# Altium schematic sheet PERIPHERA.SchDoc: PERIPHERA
size A4; Revision: V2.0; SheetNumber: 7; SheetTotal: 7; Project: PY32F403v1xT_START
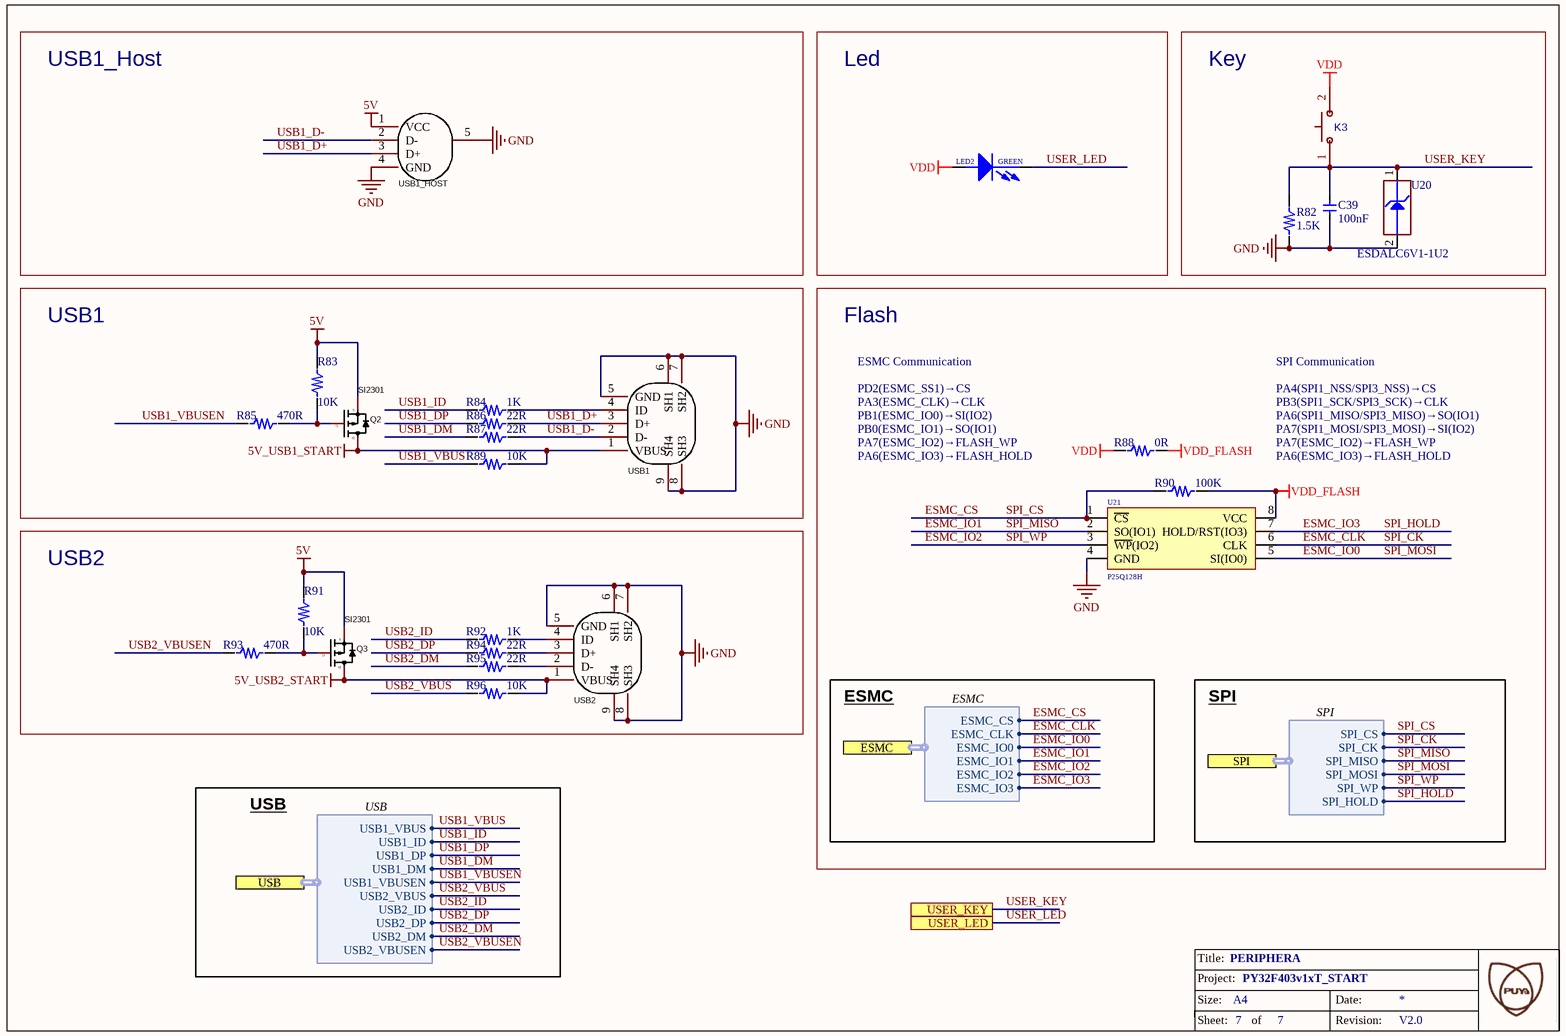
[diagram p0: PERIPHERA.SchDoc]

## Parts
C39  100nF  [C0603]
K3  1TS002B-2600-5001_key  [Switch]  (value not drawn)
LED2  GREEN  [0603_LED]
Q2  SI2301  [SOT-23-3_L2.9-W1.3-P1.90-LS2.4-BR]
Q3  SI2301  [SOT-23-3_L2.9-W1.3-P1.90-LS2.4-BR]
R82  1.5K  [R0603]
R83  10K  [R0603]
R84  1K  [R0603]
R85  470R  [R0603]
R86  22R  [R0603]
R87  22R  [R0603]
R88  0R  [R0603]
R89  10K  [R0603]
R90  100K  [R0603]
R91  10K  [R0603]
R92  1K  [R0603]
R93  470R  [R0603]
R94  22R  [R0603]
R95  22R  [R0603]
R96  10K  [R0603]
U20  value ESDALC6V1-1U2  [ESD_ST0201]  (hidden comment: ESD-TRANSIL)
U21  P25Q128H  [SOP8W_L]
USB1  Micro-B  [MICRO-USB-SMD_MICROXNJ]  (value not drawn)
USB1_HOST  Type-A  [USB-A-TH_AF-WJDG]  (value not drawn)
USB2  Micro-B  [MICRO-USB-SMD_MICROXNJ]  (value not drawn)

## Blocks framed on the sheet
USB1_Host: USB1_HOST
Led: LED2
Key: C39 K3 R82 U20
USB1: Q2 R83-R87 R89 USB1
Flash: R88 R90 U21
USB2: Q3 R91-R96 USB2

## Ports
ESMC (harness ESMC), SPI (harness SPI), USB (harness USB), USER_KEY, USER_LED

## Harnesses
ESMC: ESMC_IO2, ESMC_IO1, ESMC_IO0, ESMC_CS, ESMC_IO3, ESMC_CLK
SPI: SPI_MOSI, SPI_MISO, SPI_CS, SPI_CK, SPI_WP, SPI_HOLD
USB: USB2_VBUS, USB1_DM, USB1_DP, USB1_VBUS, USB2_ID, USB2_DP, USB2_DM, USB1_ID, USB2_VBUSEN, USB1_VBUSEN

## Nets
5V: Q2.2(S) Q3.2(S) R83.2 R91.2 USB1_HOST.1(VCC)
5V_USB1_START: Q2.3(D) R89.2 USB1.1(VBUS)
5V_USB2_START: Q3.3(D) R96.2 USB2.1(VBUS)
GND: C39.1 R82.1 U20.2(GND) U21.4(GND) USB1.5(GND) USB1.6(SH1) USB1.7(SH2) USB1.8(SH3) USB1.9(SH4) USB1_HOST.4(GND) USB1_HOST.5(SHLD) USB2.5(GND) USB2.6(SH1) USB2.7(SH2) USB2.8(SH3) USB2.9(SH4)
VDD: K3.2(B) LED2.1(ANODE) R88.1
VDD_FLASH: R88.2 R90.2 U21.8(VCC)
ESMC_CLK: U21.6(CLK) ; port ESMC.ESMC_CLK, port SPI.SPI_CK  [also labelled SPI_CK]
ESMC_CS: R90.1 U21.1(~{CS}) ; port ESMC.ESMC_CS, port SPI.SPI_CS  [also labelled SPI_CS]
ESMC_IO0: U21.5(SI(IO0)) ; port ESMC.ESMC_IO0, port SPI.SPI_MOSI  [also labelled SPI_MOSI]
ESMC_IO1: U21.2(SO(IO1)) ; port ESMC.ESMC_IO1, port SPI.SPI_MISO  [also labelled SPI_MISO]
ESMC_IO2: U21.3(~{WP}(IO2)) ; port ESMC.ESMC_IO2, port SPI.SPI_WP  [also labelled SPI_WP]
ESMC_IO3: U21.7(HOLD/RST(IO3)) ; port ESMC.ESMC_IO3, port SPI.SPI_HOLD  [also labelled SPI_HOLD]
USB1_D+: R86.2 USB1.3(D+) USB1_HOST.3(D+)
USB1_D-: R87.2 USB1.2(D-) USB1_HOST.2(D-)
USB1_DM: R87.1 ; port USB.USB1_DM
USB1_DP: R86.1 ; port USB.USB1_DP
USB1_ID: R84.1 ; port USB.USB1_ID
USB1_VBUS: R89.1 ; port USB.USB1_VBUS
USB1_VBUSEN: R85.1 ; port USB.USB1_VBUSEN
USB2_DM: R95.1 ; port USB.USB2_DM
USB2_DP: R94.1 ; port USB.USB2_DP
USB2_ID: R92.1 ; port USB.USB2_ID
USB2_VBUS: R96.1 ; port USB.USB2_VBUS
USB2_VBUSEN: R93.1 ; port USB.USB2_VBUSEN
USER_KEY: C39.2 K3.1(A) R82.2 U20.1(IO1) ; port USER_KEY
USER_LED: LED2.2(CATHODE) ; port USER_LED
NetQ2_1: Q2.1(G) R83.1 R85.2
NetQ3_1: Q3.1(G) R91.1 R93.2
NetR84_2: R84.2 USB1.4(ID)
NetR92_2: R92.2 USB2.4(ID)
NetR94_2: R94.2 USB2.3(D+)
NetR95_2: R95.2 USB2.2(D-)

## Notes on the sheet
- ESMC Communication
- SPI Communication
- PA3(ESMC_CLK)→CLK
- PB0(ESMC_IO1)→SO(IO1)
- PB1(ESMC_IO0)→SI(IO2)
- PD2(ESMC_SS1)→CS
- PA7(ESMC_IO2)→FLASH_WP
- PB3(SPI1_SCK/SPI3_SCK)→CLK
- PA6(SPI1_MISO/SPI3_MISO)→SO(IO1)
- PA7(SPI1_MOSI/SPI3_MOSI)→SI(IO2)
- PA4(SPI1_NSS/SPI3_NSS)→CS
- PA6(ESMC_IO3)→FLASH_HOLD
- ESMC
- SPI
- USB

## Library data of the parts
C39 = C0603: PCB DECAL: 0603
K3 = 1TS002B-2600-5001_key: BOM_Manufacturer: HYP; Contributor: LCSC
LED2 = PDI-E803_Dup1
Q2 Q3 = SI2301_C181086: Manufacturer: Hottech(合科泰); Add into BOM: yes; Type: P沟道; Drain Source Voltage (Vdss): 20V; Continuous Drain Current (Id): 2.3A; Power Dissipation (Pd): 1.25W; Drain Source On Resistance (RDS(on)@Vgs,Id): 120mΩ@4.5V,2.8A; Gate Threshold Voltage (Vgs(th)@Id): 1V@250uA
R82-R96 = R0603: PCB DECAL: 0603
U20 = ESD-TRANSIL: ESD protection 6V1; Internal_Part_Number: MCD-00170; Part_Type: Diode; Manufacturer: STMICROELECTRONICS; ECCN_US: EAR99; ECCN_EU: NEC; Provided_By: Subcon; Initial_Board_Reference: MB1274
U21 = W25Q256: 外置flash
USB1 USB2 = MicroXNJ: Manufacturer: SHOU HAN(首韩); Add into BOM: yes; Gender: 母; Number of Ports: 1; Number of Contacts: 5P; Current Rating - Power (Max): 1A
USB1_HOST = AF 90° WJDG: Manufacturer: SHOU HAN(首韩); Add into BOM: yes; Gender: 母; Number of Ports: 1; Number of Contacts: 4P; Current Rating - Power (Max): 1.5A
